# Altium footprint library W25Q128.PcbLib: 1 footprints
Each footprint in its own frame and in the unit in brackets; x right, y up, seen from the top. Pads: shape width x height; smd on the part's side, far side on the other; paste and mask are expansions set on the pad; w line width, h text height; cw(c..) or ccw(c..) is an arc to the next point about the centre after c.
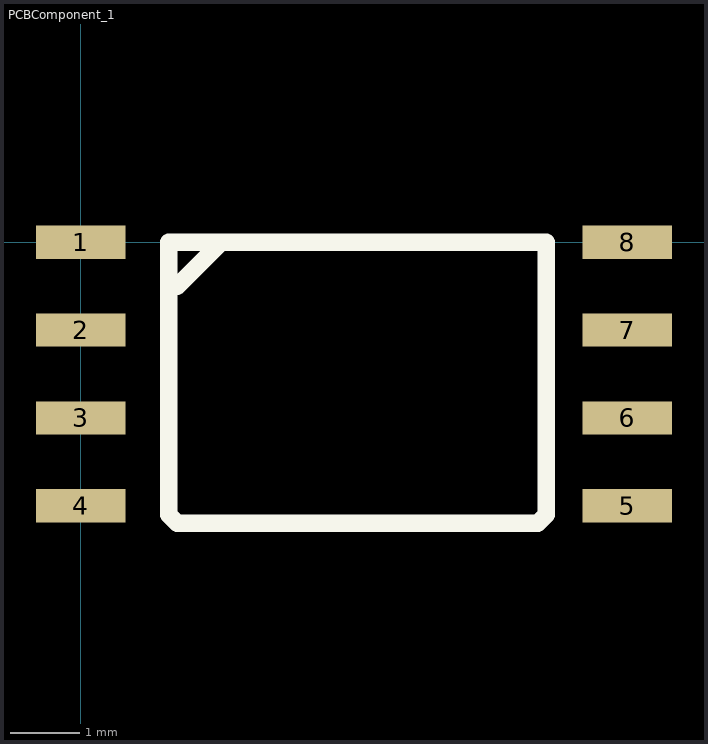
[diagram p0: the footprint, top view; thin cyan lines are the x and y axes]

## PCBComponent_1 [mm]
pads (8):
  rect 1.3x0.48 all layers, no hole: 1(0,0) 2(0,-1.27) 3(0,-2.54) 4(0,-3.81) 5(7.9,-3.81) 6(7.9,-2.54) 7(7.9,-1.27) 8(7.9,0)
Top Overlay:
  lines w0.254: 1.27,-0.889 1.27,-0.762 ; 1.397,-0.635 2.032,0 ; 1.27,-3.937 1.27,0 6.731,0 6.731,-3.937 6.604,-4.064 1.397,-4.064 1.27,-3.937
